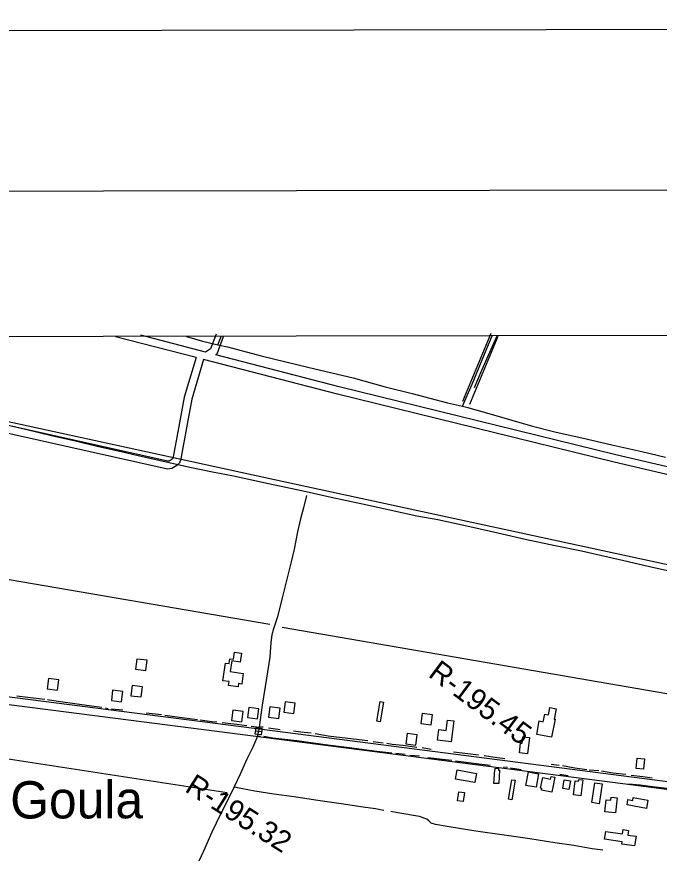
# Model space of a CAD drawing. Extents: x 3324125 to 3362000, y 600753 to 626151.
# Drawn here: x 3330131 to 3332633, y 622311 to 625567 of the extents above; entities that cross this region are included whole.
import ezdxf

# ---------------------------------------------------------------- set-up
doc = ezdxf.new("R2010")
doc.units = 0
for name, color, linetype in [('G-ANNO-NPLT', 7, 'Continuous'), ('V-ANNO-SYMB', 7, 'Continuous'), ('V-BLDG-OTLN', 7, 'Continuous'), ('V-BRDG-OTLN', 7, 'Continuous'), ('V-DTCH-CNTR', 7, 'Continuous'), ('V-GRID-FRAM', 7, 'Continuous'), ('V-RIVR-RANG-IDEN', 7, 'Continuous'), ('V-ROAD-CNTR', 7, 'Continuous'), ('V-TOPO-GNAM-IDEN', 7, 'Continuous'), ('V-TOPO-SHOR', 7, 'Continuous')]:
    doc.layers.add(name, color=color, linetype=linetype)

msp = doc.modelspace()

# ---------------------------------------------------------------- linework, layer by layer
at = {"layer": 'G-ANNO-NPLT'}
msp.add_lwpolyline([(3324750.5, 601336.7), (3361417.2, 601400.7), (3361375, 625567.3), (3324708.4, 625503.3)], close=True, dxfattribs=at)
at = {"layer": 'V-ANNO-SYMB'}
msp.add_lwpolyline([(3327499.6, 601966.6), (3360582.7, 602024.3), (3360542.7, 624940.8), (3327459.6, 624883.1), (3327499.6, 601966.6)], dxfattribs=at)
at = {"layer": 'V-BLDG-OTLN'}
for points in [[(3330933.5, 622982.3), (3330943.1, 623051.3), (3330958.1, 623049.3), (3330960.7, 623067.9), (3330974.4, 623066), (3330978.2, 623093.5), (3331005.9, 623089.7), (3331001.1, 623054.9), (3330967.7, 623059.6), (3330961.9, 623017.7), (3331012.8, 623010.6), (3331007.1, 622969.6), (3330994.3, 622971.4), (3330992.6, 622959.1), (3330955.6, 622964.3), (3330957.6, 622979)], [(3330593.7, 623027.2), (3330633.4, 623022.2), (3330638.4, 623061.9), (3330598.7, 623066.9)], [(3330249.6, 622951), (3330289.3, 622946.1), (3330294.3, 622985.7), (3330254.6, 622990.7)], [(3330499, 622905.4), (3330538.7, 622900.4), (3330543.7, 622940.1), (3330504, 622945.1)], [(3330575.2, 622924.1), (3330614.9, 622919.1), (3330619.9, 622958.8), (3330580.2, 622963.8)], [(3331029.2, 622838.6), (3331068.8, 622833.6), (3331073.8, 622873.3), (3331034.1, 622878.3)], [(3331111.3, 622840.9), (3331151, 622835.9), (3331156, 622875.6), (3331116.3, 622880.6)], [(3331170.4, 622859.9), (3331210.1, 622854.9), (3331215.1, 622894.6), (3331175.4, 622899.6)], [(3331559.3, 622899.1), (3331546.4, 622822.9), (3331533.3, 622825.1), (3331546.2, 622901.3)], [(3332213.5, 622762.4), (3332155.5, 622773.5), (3332165.5, 622825.6), (3332181.2, 622822.6), (3332186.9, 622851.8), (3332201.7, 622849), (3332207.2, 622877.5), (3332230.9, 622872.9), (3332223.2, 622832.8), (3332227, 622832.1)], [(3330967.3, 622827.9), (3331007, 622822.9), (3331012, 622862.6), (3330972.3, 622867.6)], [(3331704.8, 622815.3), (3331744.5, 622810.3), (3331749.5, 622850), (3331709.8, 622855)], [(3331832.7, 622826.2), (3331822.2, 622744.6), (3331769, 622751.4), (3331774.2, 622792.3), (3331803, 622788.6), (3331808.3, 622829.4)], [(3331645.6, 622736.7), (3331685.3, 622731.7), (3331690.2, 622771.4), (3331650.6, 622776.3)], [(3332127.3, 622761.7), (3332120.3, 622697.7), (3332088.8, 622701.1), (3332093, 622739.9), (3332099.4, 622739.2), (3332102.2, 622764.5)], [(3332543.6, 622640.9), (3332547.5, 622680.8), (3332575.2, 622678.1), (3332571.3, 622638.2)], [(3331846.1, 622635.3), (3331920.9, 622621.5), (3331914.2, 622585.6), (3331839.5, 622599.5)], [(3332011.2, 622634.2), (3332007.9, 622581.7), (3331989.2, 622582.9), (3331992.5, 622635.9), (3331994, 622635.8), (3331994.4, 622642), (3332007.2, 622641.2), (3332006.7, 622634.4)], [(3332162.9, 622619.9), (3332153.1, 622567.5), (3332113.3, 622574.9), (3332123.1, 622627.4)], [(3332071.3, 622594.7), (3332058.4, 622518.6), (3332045.3, 622520.8), (3332058.2, 622596.9)], [(3332226, 622606.5), (3332214.4, 622548.4), (3332174.6, 622556.4), (3332175.9, 622562.9), (3332170.6, 622564), (3332178.9, 622605.3), (3332209.4, 622599.2), (3332211.4, 622609.4)], [(3332262.7, 622597), (3332286.9, 622593), (3332281.2, 622559), (3332257.1, 622563)], [(3332299.3, 622537.9), (3332305.9, 622593.1), (3332318.5, 622591.6), (3332319.2, 622597.9), (3332335.1, 622596.1), (3332327.8, 622534.6)], [(3332410.8, 622580.5), (3332398.8, 622503.4), (3332370, 622507.9), (3332382, 622584.9)], [(3331874.1, 622547.4), (3331869.3, 622511.7), (3331847.6, 622514.6), (3331852.4, 622550.3)], [(3332469.1, 622527.1), (3332463, 622467.7), (3332421.3, 622472), (3332426.1, 622519.1), (3332444.3, 622517.2), (3332445.6, 622529.5)], [(3332531.7, 622527.5), (3332588.3, 622517.7), (3332582.7, 622485.5), (3332507.3, 622498.6), (3332511, 622519.6), (3332529.8, 622516.4)], [(3332487.9, 622355.7), (3332420.2, 622365.4), (3332424.4, 622395.1), (3332489.2, 622385.8), (3332491.7, 622402.8), (3332513.5, 622399.7), (3332510.9, 622381.4), (3332542.5, 622376.9), (3332537, 622339), (3332486.6, 622346.2)]]:
    msp.add_lwpolyline(points, close=True, dxfattribs=at)
at = {"layer": 'V-BRDG-OTLN'}
msp.add_lwpolyline([(3331082.5, 622772.1), (3331059.2, 622774.5), (3331063.1, 622799.7), (3331086.1, 622796.8)], close=True, dxfattribs=at)
msp.add_lwpolyline([(3331061.2, 622787.5), (3331071.8, 622786), (3331084.3, 622784.3), (3331084.3, 622784.3)], dxfattribs=at)
at = {"layer": 'V-DTCH-CNTR'}
for points in [[(3330792.3, 624322.7), (3330854.6, 624304.5), (3330913.6, 624290.6), (3330951, 624281.8), (3331083, 624247.7), (3331268.8, 624202.2), (3331440.7, 624161.5), (3331565.8, 624126.3), (3331670.2, 624101), (3331808.1, 624063.7), (3331866.7, 624050.7), (3331886.8, 624046.2), (3332018.4, 624008.3), (3332138.7, 623973.1), (3332230.8, 623949.8), (3332331.9, 623928.2), (3332448.5, 623900.9), (3332565, 623875.1), (3332656.6, 623853)], [(3330913.6, 624290.6), (3330926.2, 624322.9)], [(3331866.7, 624050.7), (3331904.3, 624137), (3331961.8, 624275.1), (3331982.7, 624324.8)], [(3332729.8, 623396.2), (3332606.3, 623423.5), (3332477.5, 623453.4), (3332330.1, 623486.3), (3332226.9, 623507.9), (3332110.9, 623532.6), (3332003.9, 623556.2), (3331907.5, 623578.4), (3331770.8, 623608.2), (3331688.3, 623623.6), (3331577.1, 623648.3), (3331477.5, 623669.4), (3331355.1, 623696.1), (3331246, 623719.8), (3331111.4, 623749.1), (3331057.4, 623761), (3330974.6, 623778.4), (3330892.7, 623794.9), (3330804.1, 623812.8), (3330724.2, 623830.9), (3330603.9, 623858.2), (3330537.2, 623873.6), (3330449.3, 623892.9), (3330359.6, 623914.6), (3330271.3, 623934.4), (3330165.1, 623960.5), (3330050.9, 623986)]]:
    msp.add_lwpolyline(points, dxfattribs=at)
at = {"layer": 'V-GRID-FRAM'}
msp.add_lwpolyline([(3328210, 624318.2), (3328233.8, 606134.5), (3359834, 606189.7), (3359794.3, 624373.3), (3328210, 624318.2)], dxfattribs=at)
at = {"layer": 'V-ROAD-CNTR'}
for points in [[(3330828.8, 624240.4), (3330515.1, 624321.7)], [(3330865.7, 624261.9), (3330613.3, 624327.2)], [(3330907.1, 624331.4), (3330885, 624274.1), (3330865.7, 624261.9)], [(3330935.1, 624320.6), (3330909.5, 624254), (3330905, 624251.2)], [(3331976.4, 624333.6), (3331866.3, 624069.9)], [(3332004.1, 624322), (3331894, 624058.3)], [(3333876, 623284.8), (3333795.6, 623369), (3333758.5, 623376.7), (3333675.5, 623405.4), (3333174.3, 623524.3), (3333172.7, 623525.9), (3333173.8, 623523.8), (3333206.9, 623645.5), (3333206.2, 623661.4), (3333195.1, 623682.8), (3333182, 623694.8), (3332464.2, 623862.2), (3331386.8, 624127), (3330905.5, 624251.6)], [(3330828.8, 624240.4), (3330783.2, 624085.7), (3330764.3, 623986.6), (3330740.4, 623853.8)], [(3330857.9, 624232.9), (3330812.4, 624078.7), (3330793.8, 623981.1), (3330769.5, 623846.2)], [(3333854.3, 623264.1), (3333780.4, 623341.5), (3333750.5, 623347.7), (3333667.1, 623376.5), (3333159.9, 623496.9), (3333148.5, 623507.3), (3333141.7, 623520.3), (3333176.7, 623648.8), (3333176.5, 623653.5), (3333170.9, 623664.3), (3333167.5, 623667.4), (3332457.2, 623833.1), (3331379.4, 624097.9), (3330857.9, 624232.9)], [(3330700.7, 623840.7), (3329644.4, 624076.8), (3329625.9, 624080.8), (3329624.6, 624081)], [(3330700.7, 623810), (3329638, 624047.5), (3329620.2, 624051.3), (3329613.7, 624052.5)], [(3330740.4, 623853.8), (3330740.2, 623852.4), (3330738.6, 623847.6), (3330735.3, 623844.5), (3330723.8, 623837.6), (3330718.5, 623836.7), (3330700.7, 623840.7)], [(3330769.5, 623846.2), (3330769.3, 623845), (3330764.7, 623831), (3330753.5, 623820.4), (3330734.3, 623809.1), (3330717.8, 623806.1), (3330700.7, 623810)], [(3333257.9, 622512), (3332374.2, 622626.5), (3331054.8, 622796.6), (3329615.1, 622981.3)], [(3333254.1, 622482.2), (3332370.3, 622596.7), (3331051, 622766.8), (3329643.6, 622947.4)]]:
    msp.add_lwpolyline(points, dxfattribs=at)
at = {"layer": 'V-TOPO-SHOR'}
for p, q in [((3329454.9, 623487.7), (3331116.8, 623202.8)), ((3330476, 622877), (3330487.2, 622874.4)), ((3330499.9, 622873.4), (3330543.9, 622868.5)), ((3330634.2, 622857.6), (3330693.9, 622850.6)), ((3331043.2, 622805.7), (3331074.7, 622802.1)), ((3331090.2, 622802), (3331074.7, 622802.1)), ((3331155.9, 622791.2), (3331111.5, 622798)), ((3330949.9, 622546.5), (3329579.5, 622756.1)), ((3331080.1, 622764.6), (3331067.4, 622766.4)), ((3331557.8, 622738.9), (3331519, 622744.6)), ((3331744.4, 622714.2), (3331709, 622720.6)), ((3331643.9, 622695.2), (3331606.6, 622699)), ((3331699.1, 622688.1), (3331661.1, 622691.9)), ((3332041.7, 622644.3), (3332026.4, 622646.1)), ((3332243.4, 622652.1), (3332212.4, 622656)), ((3332095.5, 622635.8), (3332053.3, 622642.2)), ((3332277.6, 622612.1), (3332245.5, 622617.8)), ((3332397.5, 622632), (3332359.5, 622634.7))]:
    msp.add_line(p, q, dxfattribs=at)
for points in [[(3333383.9, 623068), (3333399.2, 623185.7), (3333389, 623216.3), (3333378.8, 623236.8), (3333353.2, 623272.6), (3333199.8, 623318.6), (3331164.7, 623758.4), (3329518.1, 624116.3), (3328638.6, 624315.7)], [(3331913.4, 624123.4), (3331942.2, 624191.6), (3331984, 624285.4), (3332001, 624324.8)], [(3331259, 623703.6), (3331246.9, 623655), (3331235.6, 623612.7), (3331223.9, 623561.6), (3331211.2, 623494.8), (3331199.5, 623445.8), (3331183, 623378.2), (3331164.5, 623305.5), (3331145.9, 623231.6), (3331130.5, 623184.7), (3331124.5, 623161.5), (3331120.1, 623131.2), (3331116, 623074), (3331103.3, 622992.7), (3331086.6, 622886.9), (3331074.7, 622802.1), (3331071.8, 622786)], [(3331164.7, 623190.8), (3333302.1, 622822.6), (3333337.9, 622863.5), (3333343, 622904.4), (3333353.2, 622924.9)], [(3330131.5, 622924.1), (3330173.7, 622918.8), (3330240.5, 622911.1)], [(3330250.2, 622909.7), (3330291.7, 622902.5), (3330357, 622893.6), (3330422.3, 622884), (3330461.4, 622879.5)], [(3330707.7, 622848.4), (3330783.7, 622837.8), (3330835, 622831.1)], [(3330845.4, 622829.7), (3330890.8, 622824), (3330909.6, 622822.7)], [(3330930.1, 622820.2), (3330987.1, 622813.5), (3331026.8, 622808.2)], [(3331071.8, 622786), (3331070, 622776.5), (3331067.4, 622766.4), (3331065.6, 622759.5), (3331049.7, 622724.2), (3331026.4, 622677.2), (3331000.7, 622618.2), (3330977.4, 622569), (3330959.5, 622531.3), (3330923.9, 622462.6), (3330890.5, 622392.8), (3330858.2, 622318.4), (3330814.2, 622223.6)], [(3331277.2, 622777.6), (3331237.1, 622782), (3331208.2, 622785.6)], [(3331591.3, 622700.8), (3331532.6, 622707.3), (3331435.1, 622720.4), (3331331.7, 622732.3), (3331221.2, 622748), (3331127.9, 622758.9), (3331093.5, 622765.4)], [(3331497.4, 622747.8), (3331420.1, 622757.2), (3331343.9, 622767.1), (3331292.5, 622775.4)], [(3331689.2, 622722.7), (3331633.9, 622729.6), (3331592.5, 622734.5), (3331572, 622737.5)], [(3331824.5, 622671.5), (3331787.9, 622675.9), (3331756.9, 622680.2), (3331732, 622682.4)], [(3331929.5, 622692.4), (3331887, 622698.2), (3331831.8, 622704.3)], [(3332031, 622678.9), (3331984.4, 622684.7), (3331950.4, 622689.5)], [(3331974.6, 622652.4), (3331919.3, 622659), (3331870, 622665), (3331838.7, 622668.6)], [(3332350.9, 622635.4), (3332303.6, 622641.9), (3332256.1, 622651.1)], [(3332503.1, 622617.1), (3332452.6, 622622.8), (3332407.6, 622630.2)], [(3332605.8, 622602.9), (3332569, 622608), (3332523.3, 622613.5)], [(3331560, 622477.3), (3331528.4, 622484), (3331479.9, 622490), (3331394, 622503.5), (3331294.3, 622517.7), (3331211.4, 622529.8), (3331131.9, 622541.2), (3331057.6, 622552.2), (3331002.7, 622562.6), (3330990, 622565.5), (3330977.4, 622569)], [(3332675, 622562), (3332617.3, 622568.5), (3332558.7, 622575.5), (3332513.5, 622579.5)], [(3332413.4, 622322.3), (3332371.2, 622328.1), (3332299.9, 622340.3), (3332226.7, 622351.7), (3332128.9, 622367.4), (3332028.5, 622380.5), (3331918, 622396.5), (3331806.3, 622414.7), (3331761.2, 622422.2), (3331744.3, 622427.3), (3331735.3, 622437), (3331727.8, 622443.6), (3331699, 622453.9), (3331614.3, 622468.2), (3331587.6, 622473)]]:
    msp.add_lwpolyline(points, dxfattribs=at)

# ---------------------------------------------------------------- texts
at = {"layer": 'V-RIVR-RANG-IDEN'}
for s, rotation, p in [('R-195.45', 323.2383, (3331729.2, 623001.4)), ('R-195.32', 327.5942, (3330781, 622553.8))]:
    msp.add_text(s, height=83, rotation=rotation, dxfattribs=at).set_placement(p)
at = {"layer": 'V-TOPO-GNAM-IDEN'}
msp.add_text('Bayou Goula', height=145, rotation=0.0909, dxfattribs=at).set_placement((3329501.7, 622445))

doc.saveas('drawing.dxf')
